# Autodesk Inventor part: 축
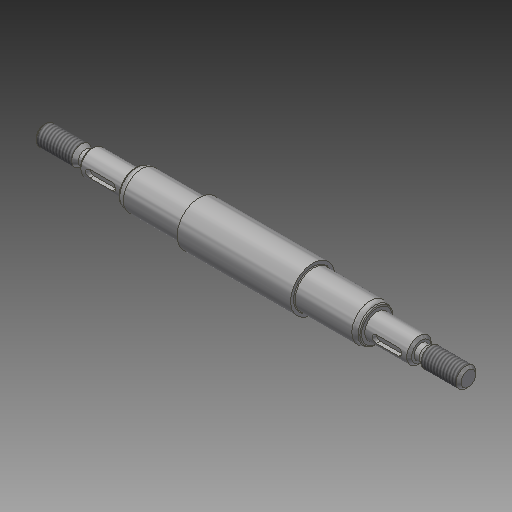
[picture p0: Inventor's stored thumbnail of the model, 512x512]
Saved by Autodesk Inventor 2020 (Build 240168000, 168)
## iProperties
Created: 2015-11
Part Number: 축
Material: 강철, 연강
Document SubType Name: Modeling
Designer: mduedu
Density: 7.86 g/cm^3
Mass: 198.507 g
Surface Area: 75.8873 cm^2
Volume: 25.2553 cm^3
Appearance: 강철
Author: mduedu
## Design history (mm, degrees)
sketch "스케치1"
  geometry: L1 (-86, 0)-(86, 0); L2 (-86, 0)-(-86, 4); L3 (-86, 4)-(-70.732, 4); L4 (-70.732, 4)-(-69, 3); L5 (-69, 3)-(-67, 3); L6 (-67, 3)-(-67, 5); L7 (-67, 5)-(-49, 5); L8 (-49, 5)-(-49, 6.55); L9 (-47.355, 7.5)-(-23, 7.5); L10 (-23, 7.5)-(-23, 9); L11 (0, 0)-(0, 9); L12 (86, 4)-(70.732, 4); L13 (70.732, 4)-(69, 3); L14 (69, 3)-(67, 3); L15 (67, 3)-(67, 5); L16 (67, 5)-(49, 5); L17 (23, 7.5)-(23, 9); L18 (86, 0)-(86, 4); L19 (-23, 9)-(23, 9); L20 (-49, 6.55)-(-47.355, 7.5); L21 (47.355, 7.5)-(23, 7.5); L22 (49, 6.55)-(47.355, 7.5); L23 (49, 5)-(49, 6.55); 1 further point
  constraints: 46 end point, 10 symmetric about line, 6 perpendicular, 5 parallel, 2 midpoint, 1 coincident, 1 horizontal
  dimensions: "d0" = 172 distance of L1.start L1.end (derived); "d1" = 8 diameter of L3 L1; "d2" = 30 deg angle of L4 L5; "d3" = 6 diameter of L5 L1; "d4" = 10 diameter of L7 L1; "d5" = 15 diameter of L9 L1; "d6" = 18 diameter of L19 L1; "d8" = 18 distance of L6.end L7.end; "d9" = 46 distance of L10.end L17.end; "d10" = 2 distance of L4.end L5.end; "d11" = 17 distance from line of L4.end L2; "d16" = 13.1 diameter of L8.end L1; "d17" = 30 deg angle of L20 L9; "d18" = 26 distance between parallel lines of L10 L8
revolve "회전1" sketch "스케치1" stored, may be unused: angle "d12" = 90 deg
chamfer "모따기1" distance "d13" = 1; stored, may be unused: second distance "d14" = 2, angle "d15" = 45 deg
fillet "모깎기1" dims "d19" = 4, "d20" = 0.5
node "작업 평면1"
sketch "스케치2" dims "d23" = 12
  geometry: L1 (-4.5, 1.5)-(4.5, 1.5); L2 (4.5, 1.5)-(4.5, -1.5); L3 (4.5, -1.5)-(-4.5, -1.5); L4 (-4.5, -1.5)-(-4.5, 1.5); L5 (-9, -4)-(-9, 4) reference; 3 further points
  constraints: 8 end point, 2 midpoint, 2 parallel, 2 vertical alignment, 1 horizontal, 1 perpendicular, 4 other
  dimensions: "d21" = 3 distance between parallel lines of L3 L1; "d24" = 3 dimension on L5
extrude "돌출1" cut sketch "스케치2" distance "d25" = 1.8; taper "d26" = 0 deg
feature "스레드1" dims "d27" = 10, "d28" = 0
feature "스레드2" dims "d29" = 10, "d30" = 0
chamfer "모따기2" distance "d31" = 1; stored, may be unused: second distance "d32" = 2, angle "d33" = 45 deg
fillet "모깎기2" dims "d34" = 0.3
node "솔리드1"
mirror "대칭1"
